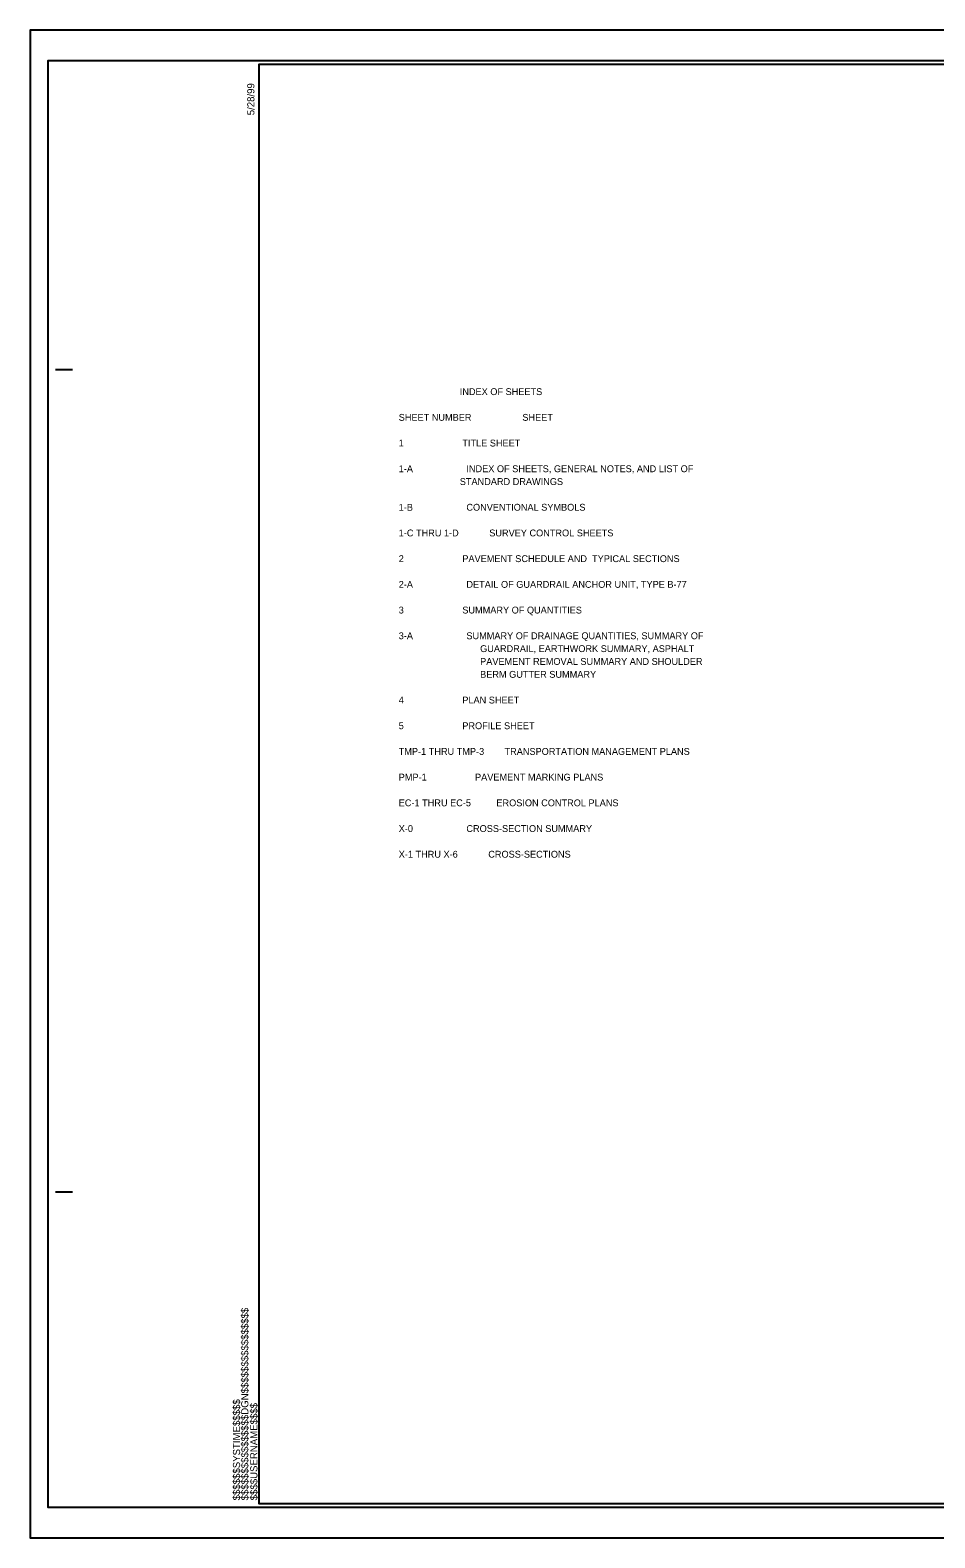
# Model space of a CAD drawing. Extents: x 573885.1 to 573944.9, y -53259.7 to -53181.6.
# Drawn here: x 573903.24 to 573916.45, y -53203.6 to -53181.6 of the extents above; entities that cross this region are included whole.
import ezdxf

# ---------------------------------------------------------------- set-up
doc = ezdxf.new("R2010")
doc.units = 0
for name, color, linetype in [('Default', 7, 'Continuous'), ('Sheet Cutting Line CELL', 7, 'Continuous'), ('Sheet Plot Border Inside CELL', 7, 'Continuous'), ('Sheet Plot Border Outside CELL', 7, 'Continuous'), ('Sheet Summary CELL', 7, 'Continuous')]:
    doc.layers.add(name, color=color, linetype=linetype)

msp = doc.modelspace()

# ---------------------------------------------------------------- linework, layer by layer
at = {"layer": 'Sheet Cutting Line CELL'}
for p, q in [((573936.919, -53181.603), (573903.239, -53181.603)), ((573903.239, -53181.603), (573903.239, -53203.603)), ((573903.239, -53203.603), (573936.919, -53203.603))]:
    msp.add_line(p, q, dxfattribs=at)
at = {"layer": 'Sheet Plot Border Inside CELL'}
msp.add_lwpolyline([(573936.829, -53182.052), (573903.499, -53182.052), (573903.499, -53203.154), (573936.829, -53203.154)], close=True, dxfattribs=at)
at = {"layer": 'Sheet Plot Border Outside CELL'}
msp.add_lwpolyline([(573936.919, -53181.603), (573903.239, -53181.603), (573903.239, -53203.603), (573936.919, -53203.603)], close=True, dxfattribs=at)
at = {"layer": 'Sheet Summary CELL'}
for p, q in [((573906.579, -53182.103), (573906.579, -53182.912)), ((573903.609, -53186.553), (573903.859, -53186.553)), ((573903.609, -53198.553), (573903.859, -53198.553)), ((573906.579, -53203.103), (573906.579, -53203.103)), ((573906.579, -53203.103), (573906.579, -53203.103)), ((573906.579, -53203.103), (573906.579, -53203.103)), ((573906.579, -53203.103), (573906.579, -53203.103)), ((573906.579, -53203.103), (573906.579, -53203.103)), ((573906.579, -53203.103), (573906.579, -53203.103))]:
    msp.add_line(p, q, dxfattribs=at)
msp.add_lwpolyline([(573936.579, -53182.103), (573906.579, -53182.103), (573906.579, -53203.103), (573936.579, -53203.103)], close=True, dxfattribs=at)
msp.add_lwpolyline([(573909.329, -53203.103), (573909.329, -53203.103)], dxfattribs=at)

# ---------------------------------------------------------------- texts
at = {"layer": 'Default'}
for s, p in [('                        INDEX OF SHEETS ', (573908.621, -53186.928)), ('SHEET NUMBER                    SHEET   ', (573908.621, -53187.303)), ('1                       TITLE SHEET', (573908.621, -53187.678)), ('1-A                     INDEX OF SHEETS, GENERAL NOTES, AND LIST OF ', (573908.621, -53188.053)), ('                        STANDARD DRAWINGS', (573908.621, -53188.24)), ('1-B                     CONVENTIONAL SYMBOLS ', (573908.621, -53188.615)), ('1-C THRU 1-D            SURVEY CONTROL SHEETS', (573908.621, -53188.99)), ('2                       PAVEMENT SCHEDULE AND  TYPICAL SECTIONS ', (573908.621, -53189.365)), ('2-A                     DETAIL OF GUARDRAIL ANCHOR UNIT, TYPE B-77', (573908.621, -53189.74)), ('3                       SUMMARY OF QUANTITIES ', (573908.621, -53190.115)), ('3-A                     SUMMARY OF DRAINAGE QUANTITIES, SUMMARY OF ', (573908.621, -53190.49)), ('                                GUARDRAIL, EARTHWORK SUMMARY, ASPHALT', (573908.621, -53190.678)), ('                                PAVEMENT REMOVAL SUMMARY AND SHOULDER', (573908.621, -53190.865)), ('                                BERM GUTTER SUMMARY ', (573908.621, -53191.053)), ('4                       PLAN SHEET', (573908.621, -53191.428)), ('5                       PROFILE SHEET', (573908.621, -53191.803)), ('TMP-1 THRU TMP-3        TRANSPORTATION MANAGEMENT PLANS', (573908.621, -53192.178)), ('PMP-1                   PAVEMENT MARKING PLANS', (573908.621, -53192.553)), ('EC-1 THRU EC-5          EROSION CONTROL PLANS', (573908.621, -53192.928)), ('X-0                     CROSS-SECTION SUMMARY', (573908.621, -53193.303)), ('X-1 THRU X-6            CROSS-SECTIONS', (573908.621, -53193.678))]:
    msp.add_text(s, height=0.1, dxfattribs=at).set_placement(p)
at = {"layer": 'Sheet Summary CELL'}
for s, p in [('5/28/99', (573906.514, -53182.845)), ('$$$$$$$$$$$$$$$$DGN$$$$$$$$$$$$$$$$', (573906.426, -53203.056)), ('$$$$$$SYSTIME$$$$$', (573906.305, -53203.056)), ('$$$$USERNAME$$$$', (573906.558, -53203.055))]:
    msp.add_text(s, height=0.105, rotation=90, dxfattribs=at).set_placement(p)

doc.saveas('drawing.dxf')
